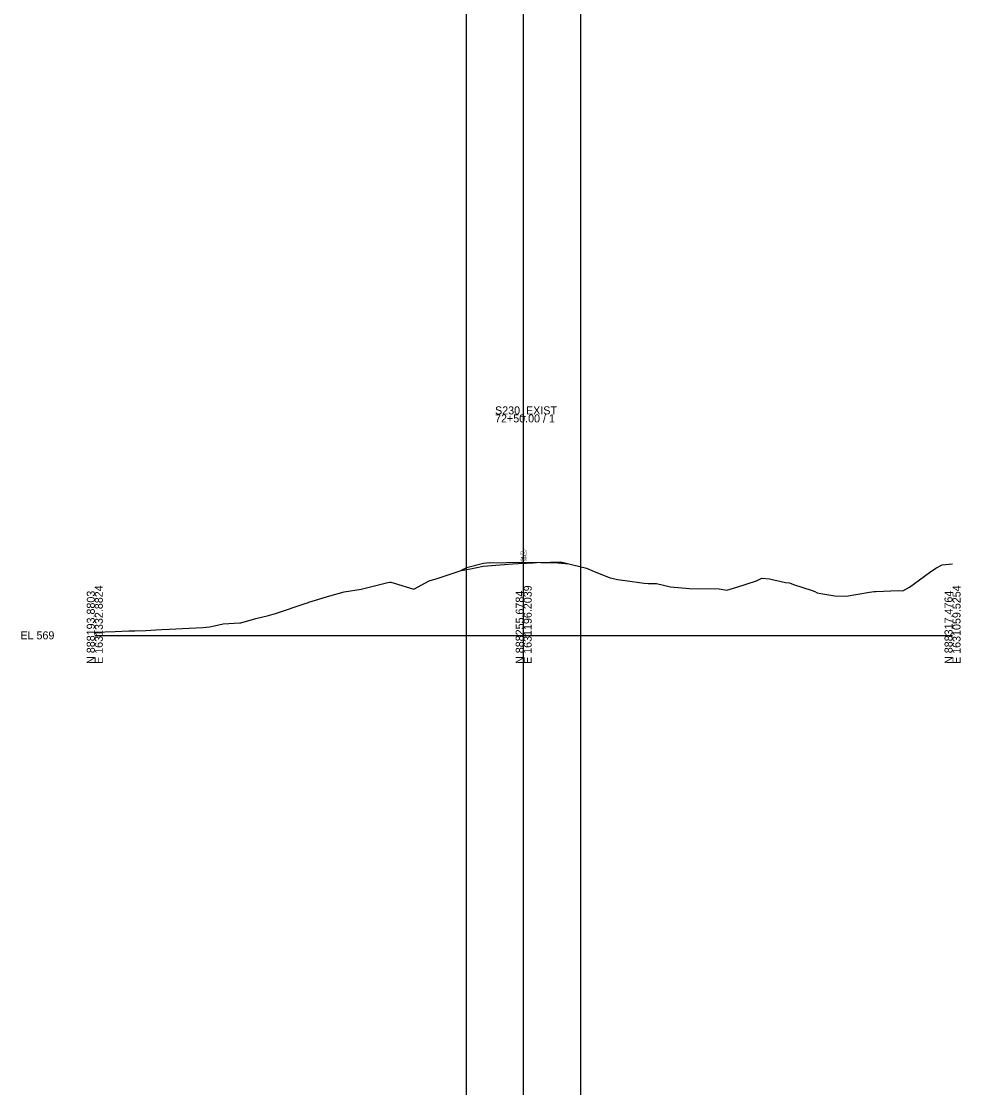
# Model space of a CAD drawing. Extents: x 1631115 to 1631443, y 885974 to 892071.
# Drawn here: x 1631114.8 to 1631443.3, y 891325.4 to 891698.4 of the extents above; entities that cross this region are included whole.
import ezdxf

# ---------------------------------------------------------------- set-up
doc = ezdxf.new("R2010")
doc.units = 0
for name, color, linetype in [('Default', 7, 'Continuous'), ('RD_GPK_XS_Cell', 7, 'Continuous'), ('RD_XS_EarthShd', 7, 'Continuous'), ('RD_XS_ExGround', 7, 'Continuous'), ('RD_XS_Pave', 7, 'Continuous'), ('RD_XS_TieSlope', 7, 'Continuous'), ('RD_XS_TX_Elev_EX', 7, 'Continuous'), ('RD_XS_TX_Elev_PR', 7, 'Continuous')]:
    doc.layers.add(name, color=color, linetype=linetype)

msp = doc.modelspace()

# ---------------------------------------------------------------- linework, layer by layer
at = {"layer": 'Default'}
for p, q in [((1631270.47, 885983.65), (1631270.47, 892068.63)), ((1631290.47, 885983.65), (1631290.47, 892068.63)), ((1631310.47, 885983.65), (1631310.47, 892068.63))]:
    msp.add_line(p, q, dxfattribs=at)
at = {"layer": 'RD_GPK_XS_Cell'}
for p, q in [((1631290.47, 891483.65), (1631290.47, 891560.94)), ((1631140.47, 891483.65), (1631290.47, 891483.65)), ((1631290.47, 891483.65), (1631440.47, 891483.65))]:
    msp.add_line(p, q, dxfattribs=at)
at = {"layer": 'RD_XS_EarthShd'}
for p, q in [((1631278.47, 891508.98), (1631276.47, 891508.82)), ((1631302.47, 891508.98), (1631306.27, 891508.68))]:
    msp.add_line(p, q, dxfattribs=at)
at = {"layer": 'RD_XS_ExGround'}
msp.add_lwpolyline([(1631140.47, 891484.72), (1631147.58, 891484.96), (1631152.37, 891485.17), (1631152.85, 891485.18), (1631153.31, 891485.2), (1631154.53, 891485.24), (1631158.29, 891485.4), (1631161.77, 891485.62), (1631163.89, 891485.67), (1631166.61, 891485.81), (1631171.01, 891486.06), (1631178.28, 891486.44), (1631180.57, 891486.65), (1631182.81, 891487.12), (1631185.37, 891487.69), (1631191.16, 891487.99), (1631191.59, 891488.08), (1631196.82, 891489.52), (1631201.22, 891490.6), (1631203.62, 891491.26), (1631214.45, 891494.92), (1631214.87, 891495.06), (1631215.31, 891495.2), (1631222.67, 891497.43), (1631227.69, 891498.89), (1631233.59, 891499.82), (1631242.97, 891502.15), (1631243.53, 891502.23), (1631243.97, 891502.21), (1631245.17, 891501.86), (1631252.08, 891499.84), (1631257.4, 891502.66), (1631260.26, 891503.56), (1631268.67, 891506.37), (1631271.92, 891506.88), (1631276.3, 891507.9), (1631286.66, 891508.61), (1631290.47, 891508.86), (1631291.34, 891508.92), (1631293.74, 891509.04), (1631294.94, 891509.08), (1631299.76, 891509.28), (1631303.31, 891509.41), (1631305.34, 891508.91), (1631312.39, 891507.19), (1631315.17, 891505.95), (1631320.72, 891503.81), (1631322.33, 891503.37), (1631323.25, 891503.16), (1631325.94, 891502.83), (1631332.66, 891501.87), (1631334.04, 891501.77), (1631336.97, 891501.75), (1631341.82, 891500.63), (1631348.52, 891500.05), (1631358.83, 891499.92), (1631361.49, 891499.47), (1631365.08, 891500.47), (1631371.87, 891502.77), (1631373.75, 891503.6), (1631376.42, 891503.42), (1631382.05, 891502.19), (1631383.5, 891501.97), (1631384.81, 891501.45), (1631391.36, 891499.29), (1631392.29, 891499.01), (1631393.16, 891498.52), (1631395.05, 891498.16), (1631399.33, 891497.52), (1631403.3, 891497.31), (1631411.41, 891498.77), (1631413.1, 891498.94), (1631413.69, 891498.93), (1631421.52, 891499.35), (1631423.08, 891499.2), (1631425.44, 891500.54), (1631432.45, 891505.68), (1631434.57, 891507.1), (1631436.82, 891508.32), (1631440.47, 891508.69)], dxfattribs=at)
at = {"layer": 'RD_XS_Pave'}
for p, q in [((1631278.47, 891508.98), (1631290.47, 891509.22)), ((1631290.47, 891509.22), (1631302.47, 891508.98))]:
    msp.add_line(p, q, dxfattribs=at)
at = {"layer": 'RD_XS_TieSlope'}
for p, q in [((1631270.47, 891507.32), (1631268.35, 891506.26)), ((1631276.47, 891508.82), (1631270.47, 891507.32))]:
    msp.add_line(p, q, dxfattribs=at)

# ---------------------------------------------------------------- texts
at = {"layer": 'RD_GPK_XS_Cell'}
for s, p in [('S230_EXIST', (1631280.47, 891560.94)), ('72+50.00 / 1', (1631280.47, 891558.14)), ('EL 569', (1631114.47, 891482.25))]:
    msp.add_text(s, height=2.8, dxfattribs=at).set_placement(p)
for s, p in [('N 888193.8803', (1631140.47, 891473.65)), ('E 1631332.8824', (1631143.27, 891473.65)), ('N 888255.6784', (1631290.47, 891473.65)), ('E 1631196.2039', (1631293.27, 891473.65)), ('N 888317.4764', (1631440.47, 891473.65)), ('E 1631059.5254', (1631443.27, 891473.65))]:
    msp.add_text(s, height=2.8, rotation=90, dxfattribs=at).set_placement(p)
at = {"layer": 'RD_XS_TX_Elev_EX'}
msp.add_text('594.21', height=1, rotation=90, dxfattribs=at).set_placement((1631290.37, 891508.96))
at = {"layer": 'RD_XS_TX_Elev_PR'}
msp.add_text(' 594.57', height=1, rotation=90, dxfattribs=at).set_placement((1631291.47, 891509.22))

doc.saveas('drawing.dxf')
